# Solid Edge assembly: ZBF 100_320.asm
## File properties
Title: Zylinder
Author: bmolnar
Template: iso metric assembly.asm
Last saved by: bmolnar
Revision: 31
Application: Solid Edge
Username: bmolnar
Dokumentum tartalom típus: 1
Document Number: ZBF 100/320
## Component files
Profilrohr.par
Kolbenstange.par
Mutter.par
Kit.par
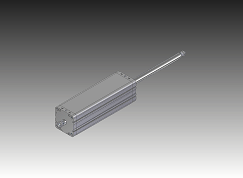
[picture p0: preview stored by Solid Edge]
